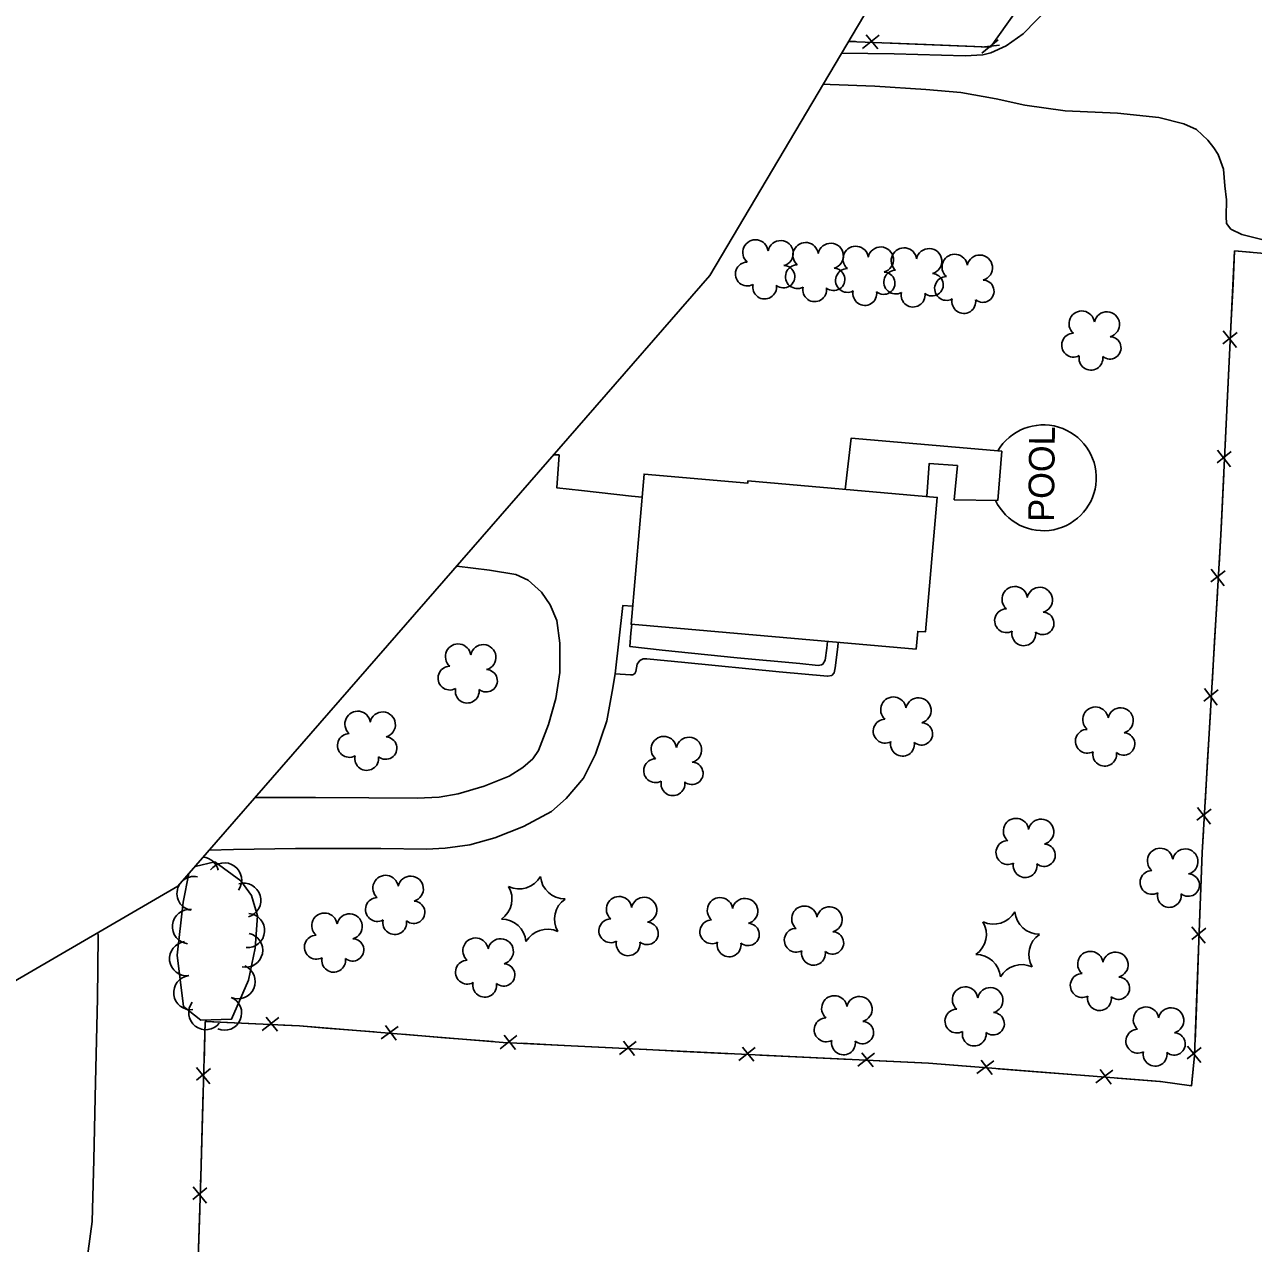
# Model space of a CAD drawing. Extents: x 353423 to 364002, y 127000 to 201942.
# Drawn here: x 359202.5 to 359489.3, y 133998.1 to 134282.6 of the extents above; entities that cross this region are included whole.
import ezdxf

# ---------------------------------------------------------------- set-up
doc = ezdxf.new("R2010")
doc.units = 0
for name, color, linetype in [('E_DTM_SlopeBottom', 7, 'Continuous'), ('E_DTM_SlopeTop', 7, 'Continuous'), ('E_FEN_Generic', 7, 'Continuous'), ('E_MISCPROP', 7, 'Continuous'), ('E_RDWY_Gravel', 7, 'Continuous'), ('E_WTR_FlowLine', 7, 'Continuous')]:
    doc.layers.add(name, color=color, linetype=linetype)

msp = doc.modelspace()

# ---------------------------------------------------------------- linework, layer by layer
at = {"layer": 'E_DTM_SlopeBottom'}
for p, q in [((359401.9, 134280.17), (359398.05, 134277.08)), ((359401.6, 134276.94), (359398.93, 134280.22)), ((359430.05, 134277.81), (359425.84, 134277.37)), ((359429.73, 134279.05), (359425.89, 134275.96)), ((359482.24, 134211.1), (359485.3, 134207.23)), ((359485.47, 134210.77), (359482.17, 134208.13)), ((359484.12, 134182.94), (359480.82, 134180.3)), ((359480.89, 134183.27), (359483.95, 134179.4)), ((359482.68, 134155.1), (359479.35, 134152.5)), ((359479.46, 134155.46), (359482.48, 134151.56)), ((359481.06, 134127.29), (359477.73, 134124.68)), ((359477.83, 134127.65), (359480.85, 134123.75)), ((359479.43, 134099.48), (359476.1, 134096.87)), ((359476.21, 134099.84), (359479.23, 134095.94)), ((359478.17, 134071.68), (359474.89, 134069.01)), ((359474.94, 134071.97), (359478.03, 134068.14)), ((359261.81, 134050.82), (359257.95, 134047.75)), ((359261.49, 134047.59), (359258.84, 134050.89)), ((359289.65, 134048.74), (359285.68, 134045.81)), ((359289.22, 134045.52), (359286.69, 134048.91)), ((359317.37, 134046.58), (359313.5, 134043.53)), ((359317.04, 134043.35), (359314.4, 134046.66)), ((359345.2, 134045.2), (359341.32, 134042.14)), ((359344.86, 134041.97), (359342.23, 134045.27)), ((359373.02, 134043.82), (359369.15, 134040.76)), ((359372.69, 134040.59), (359370.05, 134043.89)), ((359400.85, 134042.48), (359396.98, 134039.43)), ((359400.52, 134039.26), (359397.88, 134042.56)), ((359477.11, 134043.84), (359473.84, 134041.17)), ((359473.88, 134044.13), (359476.98, 134040.3)), ((359245.83, 134038.89), (359242.58, 134036.19)), ((359242.6, 134039.15), (359245.73, 134035.35)), ((359428.7, 134040.68), (359424.74, 134037.74)), ((359428.27, 134037.47), (359425.74, 134040.85)), ((359456.47, 134038.49), (359452.51, 134035.56)), ((359456.05, 134035.28), (359453.51, 134038.66)), ((359245.02, 134011.04), (359241.76, 134008.35)), ((359241.79, 134011.31), (359244.9, 134007.49))]:
    msp.add_line(p, q, dxfattribs=at)
for points in [[(359440.57, 134356), (359440.75, 134332.39), (359438.95, 134314.21), (359435.54, 134288.11), (359427.91, 134277.38), (359394.79, 134278.72)], [(359435.38, 134287.87), (359429.6, 134279.76)], [(359396.41, 134278.65), (359394.79, 134278.72)], [(359412.93, 134277.99), (359402.98, 134278.39)], [(359424.24, 134277.53), (359412.93, 134277.99)], [(359500.54, 133972.77), (359501.42, 134023.05), (359500.83, 134071.15), (359503.95, 134169.42), (359505.27, 134202.37), (359504.98, 134228.05), (359484.9, 134229.81), (359481.67, 134163.52), (359477.34, 134089.32), (359475.54, 134041.92), (359474.86, 134034.87), (359467.59, 134035.87), (359413.47, 134040.14), (359368.2, 134042.31), (359314.18, 134045), (359266.64, 134048.86), (359244.65, 134049.86), (359243.6, 134013.49), (359241.59, 133951.92)], [(359488.5, 134229.49), (359484.9, 134229.81), (359484.52, 134222.11)], [(359484.52, 134222.11), (359484.04, 134212.17)], [(359483.72, 134205.6), (359483.17, 134194.29)], [(359483.17, 134194.29), (359482.68, 134184.34)], [(359482.36, 134177.77), (359481.82, 134166.46)], [(359481.82, 134166.46), (359481.67, 134163.52), (359481.26, 134156.52)], [(359480.88, 134149.95), (359480.22, 134138.65)], [(359480.22, 134138.65), (359479.64, 134128.71)], [(359479.25, 134122.14), (359478.59, 134110.83)], [(359478.59, 134110.83), (359478.01, 134100.89)], [(359477.63, 134094.32), (359477.34, 134089.32), (359477.1, 134083.02)], [(359477.1, 134083.02), (359476.72, 134073.07)], [(359476.47, 134066.49), (359476.04, 134055.17)], [(359476.04, 134055.17), (359475.66, 134045.23)], [(359245, 134049.85), (359244.65, 134049.86), (359244.37, 134040.26)], [(359256.31, 134049.33), (359245, 134049.85)], [(359272.82, 134048.36), (359266.64, 134048.86), (359262.89, 134049.03)], [(359284.1, 134047.44), (359272.82, 134048.36)], [(359300.59, 134046.1), (359290.66, 134046.91)], [(359311.87, 134045.19), (359300.59, 134046.1)], [(359328.39, 134044.29), (359318.44, 134044.79)], [(359339.69, 134043.73), (359328.39, 134044.29)], [(359356.21, 134042.9), (359346.27, 134043.4)], [(359367.52, 134042.34), (359356.21, 134042.9)], [(359384.04, 134041.55), (359374.09, 134042.02)], [(359395.35, 134041.01), (359384.04, 134041.55)], [(359411.87, 134040.21), (359401.92, 134040.69)], [(359423.16, 134039.37), (359413.47, 134040.14), (359411.87, 134040.21)], [(359439.64, 134038.08), (359429.72, 134038.86)], [(359450.93, 134037.18), (359439.64, 134038.08)], [(359467.42, 134035.89), (359457.49, 134036.67)], [(359475.22, 134038.66), (359474.86, 134034.87), (359467.59, 134035.87), (359467.42, 134035.89)], [(359244.18, 134033.68), (359243.85, 134022.37)], [(359243.85, 134022.37), (359243.6, 134013.49), (359243.56, 134012.42)], [(359243.35, 134005.84), (359242.98, 133994.52)]]:
    msp.add_lwpolyline(points, dxfattribs=at)
at = {"layer": 'E_DTM_SlopeTop'}
msp.add_lwpolyline([(359209.48, 133771.9), (359209.83, 133779.06), (359210.19, 133789.49), (359211.07, 133807.29), (359211.91, 133830.47), (359212.29, 133845.4), (359212.52, 133862.5), (359213.06, 133878.52), (359213.5, 133894.53), (359213.95, 133914.46), (359214.18, 133933.14), (359214.23, 133948.28), (359215.06, 133967.88), (359215.62, 133985.69), (359217.28, 133996.27), (359218.23, 134003.21), (359218.66, 134017.55), (359219.05, 134035.74), (359219.45, 134055.23), (359219.61, 134069.78), (359219.6, 134070.64)], dxfattribs=at)
at = {"layer": 'E_FEN_Generic'}
msp.add_lwpolyline([(359240.82, 134084.42), (359239.49, 134077.73), (359238.09, 134065.35), (359239.57, 134053.35), (359243.63, 134050.18), (359250.79, 134050.43), (359254.74, 134059.54), (359256.28, 134066.97), (359256.85, 134074.57), (359255.46, 134079.3), (359252.97, 134082.73), (359246.85, 134087.15), (359242.26, 134086.08)], dxfattribs=at)
for centre, radius, start, end in [((359373.07, 134229.42), 2.97, 7.7946, 229.0284), ((359378.92, 134229.24), 2.97, 285.4454, 168.4187), ((359384.76, 134228.79), 2.97, 7.7946, 229.0284), ((359390.61, 134228.62), 2.97, 285.4454, 168.4187), ((359396.45, 134227.92), 2.97, 7.7946, 229.0284), ((359402.3, 134227.74), 2.97, 285.4454, 168.4187), ((359407.72, 134227.54), 2.97, 7.7946, 229.0284), ((359413.58, 134227.37), 2.97, 285.4454, 168.4187), ((359419.57, 134226.04), 2.97, 7.7946, 229.0284), ((359425.42, 134225.87), 2.97, 285.4454, 168.4187), ((359371.15, 134224.4), 2.78, 90.7655, 298.5384), ((359379.62, 134223.77), 2.61, 230.1506, 88.0832), ((359382.84, 134223.77), 2.78, 90.7655, 298.5384), ((359391.31, 134223.14), 2.61, 230.1506, 88.0832), ((359394.54, 134222.89), 2.78, 90.7655, 298.5384), ((359405.81, 134222.52), 2.78, 90.7655, 298.5384), ((359403, 134222.26), 2.61, 230.1506, 88.0832), ((359414.28, 134221.89), 2.61, 230.1506, 88.0832), ((359417.66, 134221.02), 2.78, 90.7655, 298.5384), ((359426.13, 134220.39), 2.61, 230.1506, 88.0832), ((359375.2, 134221.35), 2.78, 167.4425, 8.4535), ((359386.89, 134220.73), 2.78, 167.4425, 8.4535), ((359398.58, 134219.85), 2.78, 167.4425, 8.4535), ((359409.85, 134219.47), 2.78, 167.4425, 8.4535), ((359421.7, 134217.98), 2.78, 167.4425, 8.4535), ((359449.22, 134212.8), 2.97, 7.7946, 229.0284), ((359455.07, 134212.62), 2.97, 285.4454, 168.4187), ((359447.31, 134207.78), 2.78, 90.7655, 298.5384), ((359455.78, 134207.15), 2.61, 230.1506, 88.0832), ((359451.35, 134204.73), 2.78, 167.4425, 8.4535), ((359433.57, 134148.47), 2.97, 7.7946, 229.0284), ((359439.42, 134148.29), 2.97, 285.4454, 168.4187), ((359431.66, 134143.45), 2.78, 90.7655, 298.5384), ((359440.13, 134142.82), 2.61, 230.1506, 88.0832), ((359435.7, 134140.4), 2.78, 167.4425, 8.4535), ((359303.66, 134135.07), 2.97, 7.7946, 229.0284), ((359309.51, 134134.9), 2.97, 285.4454, 168.4187), ((359301.74, 134130.05), 2.78, 90.7655, 298.5384), ((359310.21, 134129.42), 2.61, 230.1506, 88.0832), ((359305.79, 134127.01), 2.78, 167.4425, 8.4535), ((359405.25, 134122.68), 2.97, 7.7946, 229.0284), ((359411.1, 134122.5), 2.97, 285.4454, 168.4187), ((359280.2, 134119.36), 2.97, 7.7946, 229.0284), ((359286.05, 134119.18), 2.97, 285.4454, 168.4187), ((359452.43, 134120.34), 2.97, 7.7946, 229.0284), ((359458.29, 134120.16), 2.97, 285.4454, 168.4187), ((359403.33, 134117.65), 2.78, 90.7655, 298.5384), ((359411.8, 134117.02), 2.61, 230.1506, 88.0832), ((359278.29, 134114.33), 2.78, 90.7655, 298.5384), ((359286.76, 134113.7), 2.61, 230.1506, 88.0832), ((359351.67, 134113.46), 2.97, 7.7946, 229.0284), ((359357.52, 134113.28), 2.97, 285.4454, 168.4187), ((359450.52, 134115.31), 2.78, 90.7655, 298.5384), ((359458.99, 134114.68), 2.61, 230.1506, 88.0832), ((359407.38, 134114.61), 2.78, 167.4425, 8.4535), ((359282.33, 134111.29), 2.78, 167.4425, 8.4535), ((359349.75, 134108.44), 2.78, 90.7655, 298.5384), ((359454.56, 134112.27), 2.78, 167.4425, 8.4535), ((359358.22, 134107.81), 2.61, 230.1506, 88.0832), ((359353.8, 134105.39), 2.78, 167.4425, 8.4535), ((359433.88, 134094.34), 2.97, 7.7946, 229.0284), ((359439.73, 134094.17), 2.97, 285.4454, 168.4187), ((359431.97, 134089.32), 2.78, 90.7655, 298.5384), ((359440.44, 134088.69), 2.61, 230.1506, 88.0832), ((359243.76, 134084.28), 4, 13.0739, 84.2717), ((359467.52, 134087.37), 2.97, 7.7946, 229.0284), ((359473.37, 134087.2), 2.97, 285.4454, 168.4187), ((359249.14, 134082.91), 4, 324.1697, 144.1544), ((359436.01, 134086.27), 2.78, 167.4425, 8.4535), ((359465.61, 134082.35), 2.78, 90.7655, 298.5384), ((359242.03, 134079.76), 4, 145.6864, 258.7741), ((359242.03, 134079.76), 4, 78.7894, 132.2185), ((359253.61, 134078.18), 4, 286.442, 106.4267), ((359286.73, 134081.04), 2.97, 7.7946, 229.0284), ((359292.58, 134080.86), 2.97, 285.4454, 168.4187), ((359317.91, 134086.57), 5.72, 244.5822, 330.3471), ((359328.59, 134084.2), 5.72, 184.5822, 270.3471), ((359474.08, 134081.72), 2.61, 230.1506, 88.0832), ((359310.51, 134078.51), 5.72, 304.5822, 30.3471), ((359341.22, 134076.09), 2.97, 7.7946, 229.0284), ((359469.65, 134079.3), 2.78, 167.4425, 8.4535), ((359284.82, 134076.02), 2.78, 90.7655, 298.5384), ((359293.29, 134075.38), 2.61, 230.1506, 88.0832), ((359331.87, 134073.76), 5.72, 124.5822, 210.3471), ((359347.07, 134075.91), 2.97, 285.4454, 168.4187), ((359364.78, 134075.84), 2.97, 7.7946, 229.0284), ((359370.63, 134075.66), 2.97, 285.4454, 168.4187), ((359384.48, 134073.87), 2.97, 7.7946, 229.0284), ((359390.33, 134073.69), 2.97, 285.4454, 168.4187), ((359240.95, 134072.02), 4, 83.5458, 263.5305), ((359254.49, 134071.11), 4, 265.7176, 85.7023), ((359272.47, 134072.24), 2.97, 7.7946, 229.0284), ((359278.33, 134072.06), 2.97, 285.4454, 168.4187), ((359288.86, 134072.97), 2.78, 167.4425, 8.4535), ((359313.79, 134068.07), 5.72, 4.5822, 90.3471), ((359339.3, 134071.06), 2.78, 90.7655, 298.5384), ((359362.87, 134070.82), 2.78, 90.7655, 298.5384), ((359428.63, 134078.33), 5.72, 244.5822, 330.3471), ((359439.31, 134075.95), 5.72, 184.5822, 270.3471), ((359254.05, 134066.53), 4, 258.2522, 78.2369), ((359324.47, 134065.7), 5.72, 64.5822, 150.3471), ((359347.77, 134070.43), 2.61, 230.1506, 88.0832), ((359371.34, 134070.19), 2.61, 230.1506, 88.0832), ((359382.57, 134068.85), 2.78, 90.7655, 298.5384), ((359391.04, 134068.22), 2.61, 230.1506, 88.0832), ((359421.23, 134070.26), 5.72, 304.5822, 30.3471), ((359240.3, 134064.56), 4, 97.0239, 277.0086), ((359270.56, 134067.22), 2.78, 90.7655, 298.5384), ((359279.03, 134066.59), 2.61, 230.1506, 88.0832), ((359307.73, 134066.41), 2.97, 7.7946, 229.0284), ((359313.59, 134066.24), 2.97, 285.4454, 168.4187), ((359343.35, 134068.02), 2.78, 167.4425, 8.4535), ((359366.91, 134067.77), 2.78, 167.4425, 8.4535), ((359442.6, 134065.51), 5.72, 124.5822, 210.3471), ((359274.61, 134064.17), 2.78, 167.4425, 8.4535), ((359386.61, 134065.8), 2.78, 167.4425, 8.4535), ((359424.52, 134059.83), 5.72, 4.5822, 90.3471), ((359451.23, 134063.29), 2.97, 7.7946, 229.0284), ((359457.08, 134063.11), 2.97, 285.4454, 168.4187), ((359252.3, 134059.18), 4, 246.6046, 66.5893), ((359305.82, 134061.39), 2.78, 90.7655, 298.5384), ((359314.29, 134060.76), 2.61, 230.1506, 88.0832), ((359435.2, 134057.45), 5.72, 64.5822, 150.3471), ((359241.27, 134056.62), 4, 97.0239, 277.0086), ((359309.87, 134058.35), 2.78, 167.4425, 8.4535), ((359449.32, 134058.27), 2.78, 90.7655, 298.5384), ((359457.78, 134057.64), 2.61, 230.1506, 88.0832), ((359421.99, 134055), 2.97, 7.7946, 229.0284), ((359427.84, 134054.83), 2.97, 285.4454, 168.4187), ((359244.76, 134051.95), 4, 142.0873, 322.0719), ((359249.13, 134051.84), 4, 246.6046, 66.5893), ((359391.47, 134052.94), 2.97, 7.7946, 229.0284), ((359397.32, 134052.76), 2.97, 285.4454, 168.4187), ((359453.36, 134055.22), 2.78, 167.4425, 8.4535), ((359464.21, 134050.3), 2.97, 7.7946, 229.0284), ((359389.55, 134047.92), 2.78, 90.7655, 298.5384), ((359420.07, 134049.98), 2.78, 90.7655, 298.5384), ((359428.54, 134049.35), 2.61, 230.1506, 88.0832), ((359470.06, 134050.12), 2.97, 285.4454, 168.4187), ((359398.02, 134047.29), 2.61, 230.1506, 88.0832), ((359424.12, 134046.94), 2.78, 167.4425, 8.4535), ((359462.3, 134045.27), 2.78, 90.7655, 298.5384), ((359393.6, 134044.87), 2.78, 167.4425, 8.4535), ((359470.77, 134044.64), 2.61, 230.1506, 88.0832), ((359466.34, 134042.23), 2.78, 167.4425, 8.4535)]:
    msp.add_arc(centre, radius, start, end, dxfattribs=at)
at = {"layer": 'E_MISCPROP'}
for points in [[(359393.16, 134275.97), (359405.43, 134275.83), (359421.99, 134275.34), (359426.11, 134275.54), (359427.96, 134276.03), (359431.61, 134277.64), (359435.58, 134280.51), (359441.79, 134286.83), (359445.89, 134293.12), (359448.68, 134299.46), (359450.93, 134305.64), (359451.92, 134311.45), (359452.23, 134315.79)], [(359482.89, 134237.79), (359483.01, 134241.75), (359482.59, 134244.95), (359482.27, 134248.86), (359481.04, 134252.34), (359480.01, 134253.87), (359478.61, 134255.66), (359476.01, 134258.12), (359473.08, 134259.48), (359467.17, 134260.92), (359457.56, 134261.93), (359445.35, 134262.46), (359435.96, 134263.8), (359429.23, 134265.29), (359420.98, 134266.78), (359412.84, 134267.46), (359400.9, 134268.27), (359390.53, 134268.63), (359388.86, 134268.71)], [(359482.89, 134237.79), (359482.99, 134236.21), (359484.02, 134234.85), (359486.56, 134233.59), (359493.45, 134231.94)], [(359346.6, 134172.29), (359344.15, 134172.55), (359332.48, 134173.89), (359326.73, 134174.45), (359327.24, 134182.16), (359325.98, 134182.22)], [(359303.33, 134156.22), (359310.97, 134155.24), (359317.15, 134154.24), (359319.97, 134152.92), (359323.11, 134150.14), (359325.11, 134147.15), (359326.67, 134143.51), (359327.41, 134138.24), (359327.39, 134131.4), (359326.44, 134125.26), (359324.79, 134119.19), (359322.38, 134113.12), (359321.07, 134111.17), (359318.78, 134109.17), (359315.57, 134107.17), (359309.75, 134104.8), (359303.67, 134103.03), (359299.21, 134102.29), (359294.11, 134102.03), (359282.81, 134102.07), (359270.38, 134102.17), (359257.19, 134102.16), (359256.26, 134102.15)], [(359245.58, 134089.89), (359251.23, 134090.02), (359265.67, 134090.3), (359285.65, 134090.28), (359296.24, 134090.08), (359300.64, 134090.34), (359306.39, 134091.13), (359312.21, 134092.79), (359318.95, 134095.43), (359325.48, 134098.93), (359328.85, 134101.91), (359332.94, 134106.67), (359335.73, 134112.31), (359338.37, 134120.06), (359339.64, 134126.96), (359340.31, 134131.02), (359342.1, 134146.98), (359344.38, 134146.85)], [(359389.88, 134138.62), (359389.74, 134137.04), (359389.35, 134134.22), (359388.75, 134133.3), (359388.47, 134133.13), (359387.66, 134133.03), (359383.43, 134133.48), (359368.77, 134134.78), (359351.29, 134136.58), (359343.75, 134137.42), (359343.98, 134140.57), (359344.21, 134142.62)], [(359340.31, 134131.02), (359343.89, 134130.79), (359344.43, 134130.85), (359344.92, 134131.12), (359345.14, 134131.6), (359345.42, 134133.34), (359346.07, 134134.15), (359346.84, 134134.58), (359347.7, 134134.58), (359356.55, 134133.68), (359378.59, 134131.49), (359389.88, 134130.47), (359390.85, 134130.68), (359391.4, 134131.28), (359391.67, 134132.42), (359392.29, 134137.35), (359392.4, 134138.4)]]:
    msp.add_lwpolyline(points, dxfattribs=at)
at = {"layer": 'E_RDWY_Gravel'}
msp.add_lwpolyline([(358451.57, 134219.96), (359005.44, 134002.81), (359118.41, 134011.76), (359238.27, 134081.5), (359362.41, 134224.06), (359464.76, 134396.83)], dxfattribs=at)
at = {"layer": 'E_WTR_FlowLine'}
msp.add_lwpolyline([(359394.02, 134174.11), (359395.36, 134186.05), (359430.53, 134183), (359429.62, 134171.54), (359419.47, 134171.69), (359420.21, 134179.67), (359413.64, 134180.18), (359413.04, 134172.44)], dxfattribs=at)
msp.add_lwpolyline([(359410.55, 134136.81), (359344.01, 134142.64), (359347.08, 134177.67), (359371.25, 134175.56), (359371.3, 134176.1), (359415.49, 134172.23), (359412.74, 134140.82), (359410.92, 134140.97)], close=True, dxfattribs=at)
msp.add_ellipse((359440.26, 134176.82), major_axis=(-4.46, 11.52), ratio=0.99975, start_param=1.642285, end_param=6.953358, dxfattribs=at)

# ---------------------------------------------------------------- texts
msp.add_text('POOL', height=6, rotation=89.3709, dxfattribs=at).set_placement((359442.72, 134166.52))

doc.saveas('drawing.dxf')
